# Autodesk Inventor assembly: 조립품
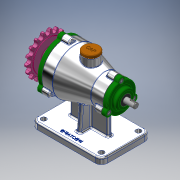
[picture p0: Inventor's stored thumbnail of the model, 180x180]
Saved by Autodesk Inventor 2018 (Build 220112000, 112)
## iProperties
Created: 2020-03
Part Number: 조립품
Material: 일반
Document SubType Name: Assembly
Designer: USER
Author: USER
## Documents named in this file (15)
- C:\Users\USER\Desktop\700306V1011\조립품.iam
- C:\Users\USER\Desktop\700306V1011\본체.ipt
- C:\Users\USER\Desktop\700306V1011\Ű 4x4x14.ipt
- C:\Users\USER\Desktop\700306V1011\개스킷 A.ipt
- C:\Users\USER\Desktop\700306V1011\개스킷 B.ipt
- C:\Users\USER\Desktop\700306V1011\뒤커버.ipt
- C:\Users\USER\Desktop\700306V1011\마개.ipt
- C:\Users\USER\Desktop\700306V1011\베어링 6200.ipt
- C:\Users\USER\Desktop\700306V1011\베어링 6203.ipt
- C:\Users\USER\Desktop\700306V1011\볼트 M5.ipt
- C:\Users\USER\Desktop\700306V1011\스프로킷.ipt
- C:\Users\USER\Desktop\700306V1011\앞커버.ipt
- C:\Users\USER\Desktop\700306V1011\오일 실 10 20 7.ipt
- C:\Users\USER\Desktop\700306V1011\오일 실 17 30 8.ipt
- C:\Users\USER\Desktop\700306V1011\축.ipt
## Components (3 placed, 3 different names)
1. Ű 4x4x14:1 — 각도:1, 각도:3
2. 개스킷 A:1
3. 개스킷 B:1
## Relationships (2: Angle 2)
- 각도:1 [Angle]: Ű 4x4x14:1
- 각도:3 [Angle]: Ű 4x4x14:1
